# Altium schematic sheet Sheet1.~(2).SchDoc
size A4
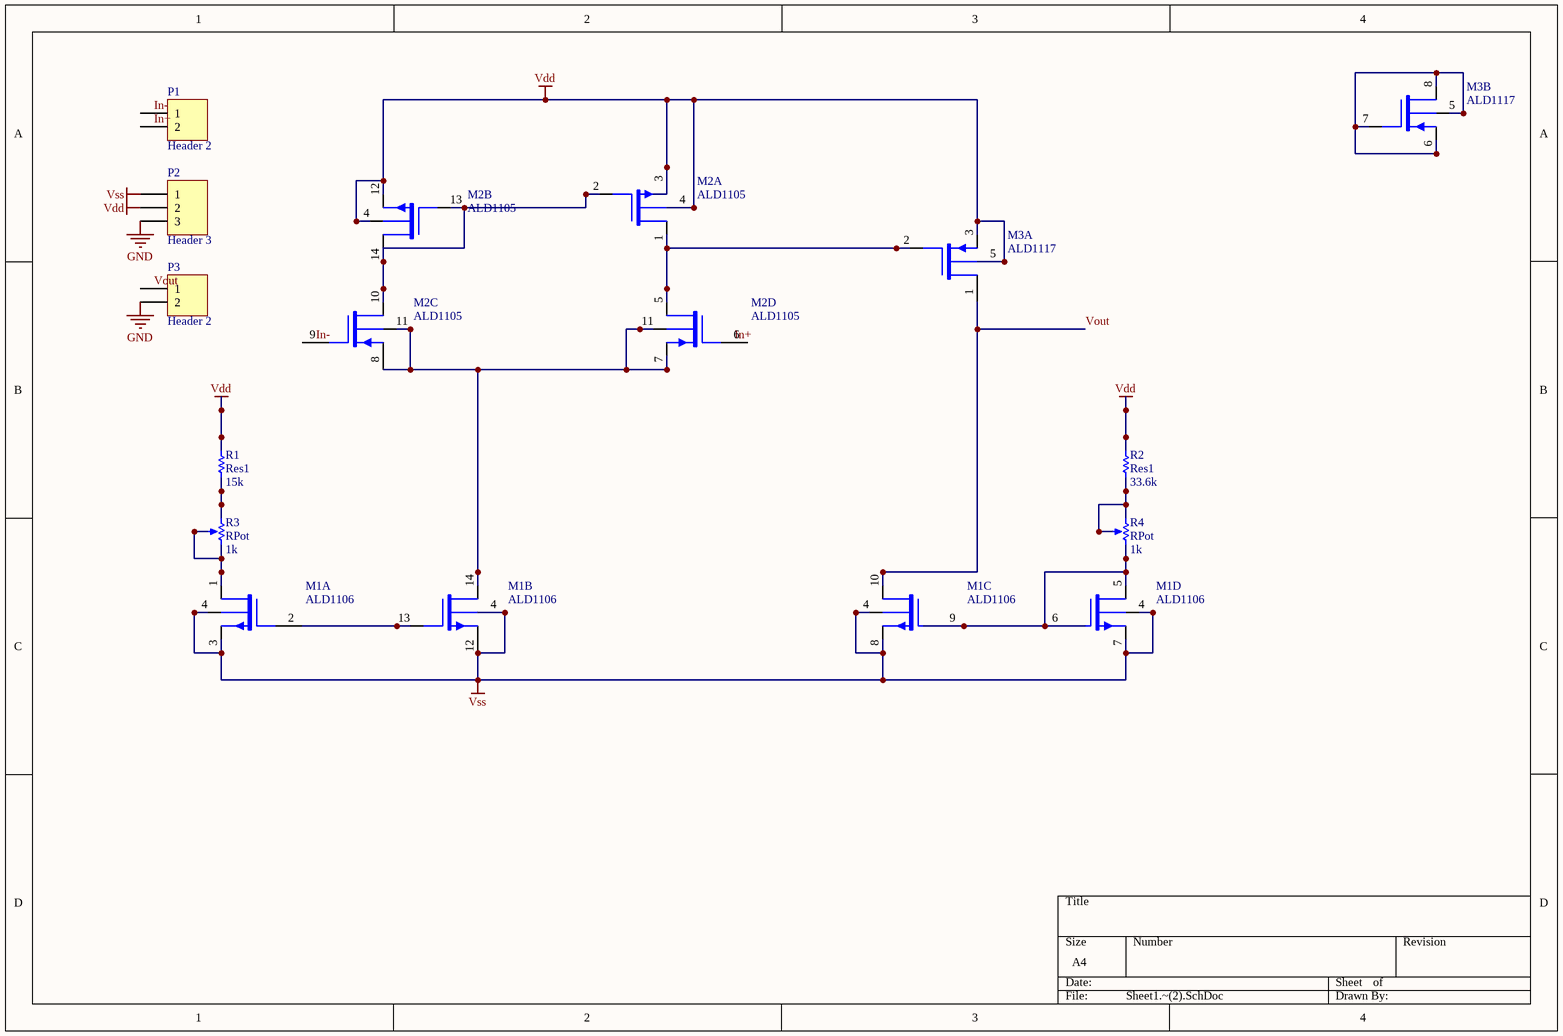
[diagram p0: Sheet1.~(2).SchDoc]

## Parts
M1  ALD1106  [DIP-14]  (parts A,B,C,D of 4)
M2  ALD1105  [DIP-14]  (parts A,B,C,D of 4)
M3  ALD1117  [DIP-8]  (parts A,B of 2)
P1  Header 2  [HDR1X2]
P2  Header 3  [HDR1X3]
P3  Header 2  [HDR1X2]
R1  Res1  value 15k  [AXIAL-0.3]
R2  Res1  value 33.6k  [AXIAL-0.3]
R3  RPot  value 1k  [VR5]
R4  RPot  value 1k  [VR5]

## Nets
GND: P2.3 P3.2
Vdd: M2.3(SN1) M2.4(V-) M2.12(SN2) M3.3(SP1) M3.5(V+) P2.2 R1.2 R2.2
Vss: M1.3(SN1) M1.4(V-) M1.7(SN4) M1.8(SN3) M1.12(SN2) P2.1
Vout: M1.10(DN3) M3.1(DP1)
NetM1_1: M1.1(DN1) R3.2(TAP) R3.3(BOT)
NetM1_2: M1.2(GN1) M1.13(GN2)
NetM1_5: M1.5(DN4) M1.6(GN4) M1.9(GN3) R4.3(BOT)
NetM1_14: M1.14(DN2) M2.7(SP1) M2.8(SP2) M2.11(V+)
NetM2_1: M2.1(DN1) M2.5(DP1) M3.2(GP1)
NetM2_2: M2.2(GN1) M2.10(DP2) M2.13(GN2) M2.14(DN2)
NetM3_5: M3.5(V+) M3.6(SP2) M3.7(GP2) M3.8(DP2)
NetR1_1: R1.1 R3.1(TOP)
NetR2_1: R2.1 R4.1(TOP) R4.2(TAP)

Not connected (* = marked no-connect by the designer): M2 6(GP1) 9(GP2); P1 1 2; P3 1

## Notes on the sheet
- Labels drawn without touching a wire or pin: In+, In-, Vout

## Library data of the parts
M1 = ALD1106: Quad N-channel matched MOSFET array
M2 = ALD1105: Dual P-channel and dual N-channel matched MOSFET array
M3 = ALD1117: Dual P-channel matched MOSFET array
P1 P3 = Header 2: Header, 2-Pin
P2 = Header 3: Header, 3-Pin
R1 R2 = Res1: Resistor
R3 R4 = RPot: Potentiometer; Sim Note: Enter the Resistance value and the set point into parameter fields.; Set Position: 0.5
